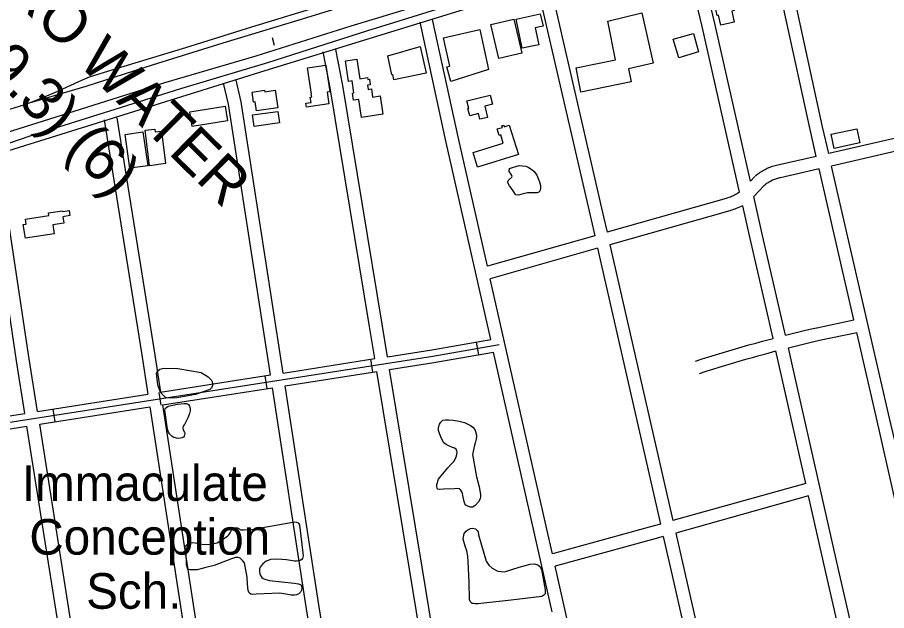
# Model space of a CAD drawing. Extents: x 3651524 to 3689615, y 505651 to 531377.
# Drawn here: x 3672779 to 3674806, y 511770 to 513153 of the extents above; entities that cross this region are included whole.
import ezdxf

# ---------------------------------------------------------------- set-up
doc = ezdxf.new("R2010")
doc.units = 0
for name, color, linetype in [('V-BLDG-IDEN', 7, 'Continuous'), ('V-BLDG-OTLN', 7, 'Continuous'), ('V-CHAN-NAID', 7, 'Continuous'), ('V-RAIL-TRAK', 7, 'Continuous'), ('V-ROAD-CNTR', 7, 'Continuous'), ('V-SITE-VEGE', 7, 'Continuous'), ('V-TOPO-SHOR', 7, 'Continuous')]:
    doc.layers.add(name, color=color, linetype=linetype)

msp = doc.modelspace()

# ---------------------------------------------------------------- linework, layer by layer
at = {"layer": 'V-BLDG-OTLN'}
for points in [[(3674419.249, 513134.831), (3674413.991, 513158.059), (3674410.776, 513157.33), (3674405.193, 513182.002), (3674407.067, 513182.426), (3674399.326, 513216.626), (3674432.782, 513224.193), (3674440.445, 513190.323), (3674445.047, 513191.366), (3674450.235, 513168.444), (3674444.613, 513167.173), (3674450.294, 513141.855)], [(3673883.17, 513136.027), (3673936.844, 513148.356), (3673954.951, 513069.538), (3673901.275, 513057.209)], [(3673941.727, 513148.945), (3673998.299, 513160.867), (3674004.602, 513132.185), (3673986.576, 513128.385), (3673994.913, 513088.826), (3673956.118, 513080.651)], [(3674235.244, 513163.683), (3674261.817, 513045.736), (3674203.694, 513032.723), (3674209.82, 513002.253), (3674093.131, 512978.787), (3674081.793, 513035.173), (3674173.54, 513053.621), (3674155.36, 513144.006)], [(3673789.368, 513003.736), (3673780.623, 513037.274), (3673787.475, 513038.829), (3673772.392, 513105.333), (3673857.525, 513124.64), (3673877.643, 513030.948)], [(3674308.071, 513102.214), (3674355.423, 513115.364), (3674367.235, 513072.797), (3674321.299, 513058.792)], [(3673718.253, 513085.177), (3673732.145, 513022.606), (3673656.838, 513007.031), (3673654.429, 513019.891), (3673652.039, 513018.754), (3673642.985, 513063.196)], [(3673624.702, 512969.807), (3673631.356, 512927.624), (3673581.465, 512919.752), (3673574.856, 512961.629), (3673562.808, 512959.729), (3673560.19, 512976.307), (3673563.639, 512976.852), (3673559.25, 513004.67), (3673551.196, 513003.398), (3673543.636, 513051.301), (3673570.412, 513055.526), (3673577.635, 513009.735), (3673595.559, 513012.563), (3673596.243, 513008.233), (3673599.76, 513008.788), (3673601.787, 512995.935), (3673595.41, 512994.93), (3673597.015, 512984.761), (3673604.272, 512985.906), (3673607.247, 512967.052)], [(3673455.468, 513035.419), (3673498.24, 513041.638), (3673507.344, 512979.054), (3673501.525, 512978.208), (3673505.482, 512951.002), (3673452.746, 512943.332), (3673451.413, 512952.499), (3673463.668, 512954.283), (3673461.841, 512966.833), (3673465.229, 512967.327), (3673464.289, 512973.792), (3673464.428, 512973.815)], [(3673386.063, 512942.255), (3673336.541, 512934.811), (3673333.411, 512955.618), (3673329.643, 512955.051), (3673326.106, 512978.568), (3673355.093, 512982.926), (3673355.63, 512979.363), (3673379.934, 512983.016)], [(3673881.673, 512971.537), (3673886.732, 512950.396), (3673868.588, 512946.052), (3673874.911, 512919.647), (3673857.365, 512915.449), (3673854.244, 512928.488), (3673833.633, 512923.557), (3673829.617, 512940.334), (3673831.446, 512940.77), (3673827.202, 512958.5)], [(3673263.288, 512946.146), (3673268.938, 512912.061), (3673186.541, 512898.399), (3673180.886, 512932.484)], [(3673386.329, 512933.715), (3673390.061, 512906.741), (3673330.777, 512898.538), (3673327.044, 512925.513)], [(3673071.63, 512886.046), (3673082.744, 512807.114), (3673041.053, 512801.24), (3673029.939, 512880.174)], [(3673114.926, 512887.61), (3673124.579, 512811.949), (3673087.108, 512807.169), (3673076.59, 512889.634), (3673099.059, 512892.501), (3673099.929, 512885.697)], [(3673852.016, 512803.64), (3673841.344, 512838.141), (3673911.691, 512859.905), (3673905.84, 512878.81), (3673902.309, 512877.718), (3673897.662, 512892.741), (3673909.929, 512896.536), (3673908.799, 512900.189), (3673912.936, 512901.467), (3673913.991, 512898.059), (3673926.016, 512901.78), (3673947.262, 512833.111)], [(3674743.263, 512860.179), (3674683.299, 512847.242), (3674676.158, 512880.348), (3674736.119, 512893.283)], [(3672864.333, 512648.445), (3672797.413, 512638.504), (3672792.708, 512670.168), (3672799.369, 512671.157), (3672797.62, 512682.929), (3672852.373, 512691.064), (3672851.439, 512697.359), (3672884.336, 512702.246), (3672884.625, 512700.304), (3672899.815, 512702.561), (3672901.564, 512690.8), (3672884.86, 512688.317), (3672887.054, 512673.553), (3672861.177, 512669.679)]]:
    msp.add_lwpolyline(points, close=True, dxfattribs=at)
at = {"layer": 'V-RAIL-TRAK'}
for points in [[(3674293.276, 513430.341), (3674148.577, 513385.209), (3674010.879, 513342.326), (3673826.701, 513284.986), (3673789.218, 513273.413), (3673656.049, 513232.301), (3673574.457, 513206.848), (3673497.978, 513182.993), (3673324.461, 513129.983), (3673170.845, 513082.119), (3673001.31, 513030.553), (3672946.39, 513013.208), (3672935.726, 513009.038), (3672921.722, 513002.79), (3672865.232, 512977.157), (3672812.873, 512955.041), (3672795.524, 512949.261), (3672675.018, 512911.838)], [(3672812.873, 512955.041), (3672939.288, 512992.845), (3673094.174, 513041.847), (3673258.817, 513093.217), (3673435.754, 513147.155), (3673641.363, 513210.928), (3673864.724, 513280.994), (3674061.944, 513342.012), (3674279.26, 513409.134), (3674317.688, 513421.53)]]:
    msp.add_lwpolyline(points, dxfattribs=at)
at = {"layer": 'V-ROAD-CNTR'}
for p, q in [((3673849.006, 512396.325), (3673854.138, 512366.767)), ((3673602.546, 512355.993), (3673607.18, 512326.353)), ((3673355.547, 512317.375), (3673360.181, 512287.735)), ((3673108.549, 512278.756), (3673113.183, 512249.116)), ((3672861.549, 512240.137), (3672866.184, 512210.499))]:
    msp.add_line(p, q, dxfattribs=at)
for points in [[(3674641.699, 512828.971), (3674627.382, 512891.179), (3674542.756, 513278.766), (3674516.963, 513388.642)], [(3674670.938, 512835.686), (3674656.656, 512897.743), (3674572.016, 513285.394), (3674546.169, 513395.498)], [(3671294.334, 512432.967), (3671352.457, 512449.955), (3671461.646, 512485.09), (3671629.739, 512537.998), (3671792.357, 512587.566), (3671992.156, 512648.584), (3672132.456, 512695.352), (3672272.375, 512737.224), (3672471.388, 512799.612), (3672680.974, 512862.027), (3672896.814, 512929.94), (3673120.483, 513000.224), (3673335.551, 513063.435), (3673557.262, 513133.321), (3673794.439, 513205.403), (3674047.647, 513287.12), (3674299.303, 513364.133)], [(3674463.095, 512745.616), (3674376.019, 513131.496), (3674328.481, 513330.011)], [(3674488.175, 512770.762), (3674405.239, 513138.292), (3674357.657, 513336.997)], [(3671355, 512405.247), (3672270.319, 512690.678), (3673356.941, 513028.814), (3674111.997, 513261.762)], [(3674020.464, 513232.382), (3674145.948, 512687.739), (3674154.041, 512652.272)], [(3673991.23, 513225.646), (3674116.706, 512681.035), (3674125.137, 512644.091)], [(3673874.758, 512573.221), (3673808.15, 512867.398), (3673747.238, 513147.889)], [(3673882.726, 512402.18), (3673778.862, 512860.902), (3673717.923, 513141.523)], [(3673612.292, 512357.517), (3673599.866, 512432.737), (3673508.287, 512988.639), (3673492.046, 513072.176)], [(3673641.933, 512362.151), (3673629.466, 512437.621), (3673537.817, 512993.941), (3673521.494, 513077.902)], [(3673398.563, 512324.1), (3673371.428, 512499.423), (3673300.932, 512956.037), (3673289.036, 513006.577)], [(3673368.923, 512319.466), (3673341.78, 512494.841), (3673271.462, 512950.303), (3673259.834, 512999.703)], [(3672981.493, 512914.222), (3673068.349, 512371.074), (3673083.12, 512274.78)], [(3673011.117, 512918.96), (3673097.987, 512375.716), (3673112.759, 512279.414)], [(3674942.136, 512897.964), (3674670.938, 512835.686)], [(3674948.832, 512868.721), (3674677.668, 512806.45)], [(3672796.521, 512229.972), (3672777.057, 512352.693), (3672714.522, 512766.978), (3672705.326, 512828.44)], [(3672826.163, 512234.606), (3672806.705, 512357.281), (3672744.187, 512771.436), (3672734.995, 512832.878)], [(3674641.7, 512828.972), (3674551.967, 512808.365)], [(3674552.194, 512808.416), (3674549.214, 512807.78), (3674546.052, 512807.01), (3674542.912, 512806.153), (3674539.794, 512805.205), (3674536.708, 512804.17), (3674533.653, 512803.05), (3674530.627, 512801.842), (3674527.64, 512800.551), (3674524.69, 512799.176), (3674521.778, 512797.717), (3674518.908, 512796.176), (3674516.085, 512794.556), (3674513.308, 512792.856), (3674510.579, 512791.077), (3674507.904, 512789.225), (3674505.278, 512787.294), (3674502.713, 512785.293), (3674500.264, 512783.271), (3674499.698, 512782.787)], [(3674824.676, 512166.741), (3674812.817, 512219.226), (3674677.667, 512806.45)], [(3674488.175, 512770.762), (3674498.579, 512781.723)], [(3674648.429, 512799.736), (3674558.681, 512779.127)], [(3674729.383, 512447.988), (3674648.428, 512799.735)], [(3674496.12, 512735.557), (3674520.337, 512761.069)], [(3674558.454, 512779.076), (3674555.894, 512778.53), (3674553.552, 512777.96), (3674551.228, 512777.325), (3674548.926, 512776.625), (3674546.642, 512775.86), (3674544.379, 512775.03), (3674542.143, 512774.138), (3674539.932, 512773.181), (3674537.748, 512772.164), (3674535.596, 512771.085), (3674533.474, 512769.946), (3674531.385, 512768.746), (3674529.33, 512767.49), (3674527.313, 512766.175), (3674525.332, 512764.803), (3674523.394, 512763.378), (3674521.493, 512761.895), (3674519.574, 512760.311), (3674519.218, 512760.005)], [(3674463.095, 512745.616), (3674455.546, 512741.087), (3674453.17, 512739.743), (3674450.763, 512738.463), (3674448.321, 512737.243), (3674445.847, 512736.087), (3674443.345, 512734.994), (3674440.819, 512733.966), (3674438.266, 512733.004), (3674435.686, 512732.106), (3674433.044, 512731.262), (3674431.639, 512730.843)], [(3674431.835, 512730.9), (3674154.042, 512652.272)], [(3674570.072, 512412.204), (3674516.71, 512644.309), (3674496.12, 512735.557)], [(3674440.005, 512702.034), (3674160.725, 512622.985)], [(3674470.23, 512714.003), (3674455.007, 512707.35), (3674451.763, 512706.03), (3674448.488, 512704.796), (3674445.184, 512703.646), (3674441.892, 512702.594), (3674440.201, 512702.091)], [(3674541.006, 512404.737), (3674487.46, 512637.647), (3674470.23, 512714.003)], [(3674125.139, 512644.091), (3673874.758, 512573.221)], [(3674160.725, 512622.985), (3674307.385, 511980.301)], [(3674131.822, 512614.804), (3673881.393, 512543.921)], [(3674131.82, 512614.805), (3674278.457, 511972.224)], [(3674026.468, 511902.945), (3674013.6, 511960.017), (3673881.392, 512543.92)], [(3674643.123, 512429.686), (3674729.382, 512447.989)], [(3674570.072, 512412.204), (3674594.94, 512418.328), (3674610.744, 512422.139), (3674626.567, 512425.871), (3674642.393, 512429.522), (3674642.907, 512429.639)], [(3674649.349, 512400.34), (3674736.111, 512418.749)], [(3674953.433, 511461.934), (3674929.651, 511566.043), (3674783.567, 512212.556), (3674736.112, 512418.748)], [(3673641.933, 512362.151), (3673745.066, 512378.276), (3673882.726, 512402.18)], [(3674360.407, 512351.869), (3674375.85, 512356.828), (3674391.353, 512361.722), (3674406.88, 512366.54), (3674422.431, 512371.281), (3674438.005, 512375.945), (3674453.602, 512380.532), (3674469.222, 512385.042), (3674484.863, 512389.474), (3674500.527, 512393.829), (3674516.211, 512398.106), (3674541.006, 512404.737)], [(3674576.795, 512382.96), (3674602.044, 512389.182), (3674617.704, 512392.957), (3674633.383, 512396.655), (3674649.095, 512400.28), (3674649.565, 512400.387)], [(3671331.153, 511994.772), (3672021.215, 512092.876), (3672671.093, 512195.178), (3673747.508, 512363.476), (3673902.03, 512390.308)], [(3674369.579, 512323.305), (3674384.952, 512328.242), (3674400.315, 512333.092), (3674415.7, 512337.866), (3674431.109, 512342.563), (3674446.541, 512347.185), (3674461.994, 512351.73), (3674477.472, 512356.198), (3674492.971, 512360.59), (3674508.491, 512364.905), (3674524.033, 512369.144), (3674547.731, 512375.483)], [(3674617.366, 512066.852), (3674557.16, 512334.469), (3674547.731, 512375.483)], [(3674799.737, 511403.525), (3674693.282, 511866.084), (3674586.414, 512341.123), (3674576.795, 512382.96)], [(3673398.563, 512324.1), (3673612.292, 512357.517)], [(3673646.822, 512332.552), (3673749.95, 512348.676), (3673889.36, 512372.883)], [(3674026.286, 511767.349), (3673984.338, 511953.405), (3673889.36, 512372.883)], [(3673112.759, 512279.414), (3673368.923, 512319.466)], [(3673403.151, 512294.453), (3673617.182, 512327.917)], [(3673717.976, 511715.748), (3673693.356, 511866.8), (3673617.182, 512327.917)], [(3673747.621, 511720.356), (3673722.96, 511871.658), (3673646.822, 512332.552)], [(3673498.391, 511681.623), (3673480.563, 511794.288), (3673403.151, 512294.453)], [(3672826.163, 512234.606), (3673083.12, 512274.78)], [(3673117.308, 512249.761), (3673373.511, 512289.819)], [(3673468.746, 511677.018), (3673450.923, 511789.65), (3673373.511, 512289.819)], [(3672830.862, 512204.975), (3673087.668, 512245.127)], [(3673087.668, 512245.127), (3673166.702, 511729.88), (3673181.828, 511632.43)], [(3673117.308, 512249.761), (3673196.352, 511734.454), (3673211.473, 511637.037)], [(3672247.299, 512143.65), (3672668.768, 512209.997), (3672796.521, 512229.972)], [(3672250.052, 512113.714), (3672673.418, 512180.359), (3672801.221, 512200.341)], [(3672898.074, 511588.229), (3672882.026, 511690.881), (3672801.221, 512200.341)], [(3672927.715, 511592.852), (3672911.66, 511695.547), (3672830.862, 512204.975)], [(3674617.367, 512066.852), (3674307.386, 511980.301)], [(3674623.959, 512037.546), (3674314.067, 511951.019)], [(3674770.915, 511395.004), (3674664.03, 511859.428), (3674623.959, 512037.545)], [(3674278.458, 511972.224), (3674251.917, 511964.813), (3674026.467, 511902.946)], [(3674314.067, 511951.02), (3674335.156, 511858.606), (3674462.414, 511297.968)], [(3674285.14, 511942.942), (3674259.921, 511935.901), (3674033.073, 511873.65)], [(3674285.139, 511942.943), (3674305.904, 511851.948), (3674434.292, 511286.331)], [(3674169.849, 511266.995), (3674033.073, 511873.649)]]:
    msp.add_lwpolyline(points, dxfattribs=at)
at = {"layer": 'V-SITE-VEGE'}
for points in [[(3673926.555, 512800.904), (3673935.382, 512803.476), (3673941.46, 512805.064), (3673948.915, 512807.437), (3673964.619, 512805.907), (3673970.122, 512803.565), (3673978.378, 512798.483), (3673983.69, 512793.392), (3673989.795, 512784.969), (3673993.545, 512777.129), (3673996.509, 512769.283), (3673998.493, 512760.657), (3673999.095, 512754.963), (3673998.323, 512750.251), (3673997.152, 512747.894), (3673995.194, 512745.532), (3673991.274, 512743.951), (3673987.544, 512743.55), (3673980.479, 512743.925), (3673973.804, 512744.107), (3673968.113, 512743.894), (3673958.696, 512741.32), (3673947.125, 512738.739), (3673941.235, 512739.507), (3673938.675, 512742.446), (3673936.508, 512746.169), (3673929.222, 512756.161), (3673926.266, 512760.47), (3673923.309, 512765.371), (3673922.514, 512769.49), (3673924.075, 512773.223), (3673932.103, 512780.113), (3673932.49, 512782.667), (3673932.093, 512784.627), (3673929.924, 512788.155), (3673927.366, 512791.289), (3673925.789, 512793.837), (3673925.392, 512795.602), (3673925.39, 512796.583), (3673926.365, 512798.94)], [(3673228.015, 512285.941), (3673193.987, 512274.24), (3673151.291, 512266.257), (3673136.134, 512265.432), (3673127.075, 512266.395), (3673123.727, 512267.961), (3673119.385, 512271.887), (3673112.87, 512278.76), (3673106.726, 512296.265), (3673103.505, 512324.013), (3673106.05, 512329.532), (3673110.767, 512332.694), (3673120.407, 512335.476), (3673152.692, 512334.769), (3673207.246, 512325.064), (3673224.005, 512315.461), (3673230.518, 512308.389), (3673233.09, 512303.67), (3673233.493, 512299.341), (3673233.506, 512295.009), (3673231.746, 512289.297)], [(3673141.847, 512174.206), (3673138.685, 512176.694), (3673133.805, 512182.47), (3673131.034, 512186.144), (3673128.912, 512192.976), (3673122.621, 512237.8), (3673123.139, 512240.561), (3673124.054, 512242.142), (3673130.751, 512246.498), (3673151.909, 512251.286), (3673167.814, 512253.3), (3673173.471, 512253.048), (3673177.814, 512250.826), (3673180.585, 512246.756), (3673182.044, 512242.421), (3673181.933, 512235.582), (3673180.497, 512229.926), (3673176.448, 512219.262), (3673168.332, 512203.859), (3673165.451, 512200.037), (3673164.932, 512196.353), (3673165.34, 512191.884), (3673168.246, 512186.107), (3673169.307, 512182.824), (3673168.789, 512180.059), (3673167.744, 512177.163), (3673165.909, 512174.792), (3673163.153, 512173.075), (3673159.604, 512172.277), (3673155.006, 512171.74), (3673149.742, 512172.252)], [(3673789.435, 512110.732), (3673796.298, 512117.829), (3673799.628, 512122.949), (3673801.777, 512128.654), (3673803.331, 512134.358), (3673804.109, 512139.474), (3673803.509, 512142.812), (3673801.731, 512146.544), (3673798.186, 512149.091), (3673793.265, 512150.848), (3673786.181, 512153.779), (3673778.7, 512157.693), (3673772.992, 512161.41), (3673767.657, 512171.82), (3673762.91, 512182.816), (3673760.925, 512190.281), (3673760.909, 512196.965), (3673763.051, 512205.03), (3673766.184, 512209.757), (3673771.089, 512213.898), (3673777.573, 512215.291), (3673785.044, 512214.719), (3673795.071, 512214.547), (3673809.43, 512212.227), (3673821.82, 512209.11), (3673835.8, 512201.676), (3673841.117, 512197.561), (3673845.849, 512192.265), (3673847.433, 512188.141), (3673849.02, 512182.05), (3673849.821, 512176.743), (3673848.854, 512169.663), (3673847.101, 512163.37), (3673844.76, 512156.286), (3673840.492, 512134.061), (3673849.272, 512082.378), (3673855.819, 512058.607), (3673858.617, 512040.723), (3673859.022, 512035.22), (3673857.658, 512031.09), (3673854.332, 512024.004), (3673846.296, 512015.332), (3673840.015, 512011.582), (3673835.493, 512011.374), (3673830.573, 512012.737), (3673824.667, 512016.068), (3673822.496, 512019.598), (3673820.714, 512024.901), (3673819.516, 512031.78), (3673817.728, 512039.048), (3673816.539, 512043.566), (3673815.152, 512047.498), (3673812.782, 512051.42), (3673809.041, 512054.361), (3673804.912, 512054.744), (3673797.834, 512054.136), (3673772.281, 512053.089), (3673763.239, 512052.475), (3673759.111, 512053.644), (3673757.728, 512054.625), (3673756.735, 512059.536), (3673757.116, 512064.454), (3673761.212, 512076.848), (3673766.891, 512084.727), (3673782.378, 512102.852)], [(3673180.759, 511865.292), (3673177.335, 511867.387), (3673175.885, 511869.357), (3673174.562, 511871.983), (3673173.634, 511875.268), (3673172.971, 511878.157), (3673173.487, 511881.446), (3673172.123, 511901.035), (3673170.116, 511914.97), (3673170.235, 511919.441), (3673173.774, 511924.053), (3673179.156, 511928.01), (3673186.123, 511928.817), (3673194.407, 511928.313), (3673204.539, 511926.103), (3673214.666, 511924.682), (3673230.051, 511925.509), (3673244.374, 511928.569), (3673257.242, 511936.493), (3673265.119, 511941.377), (3673268.926, 511944.279), (3673271.809, 511947.048), (3673274.953, 511951.92), (3673277.833, 511957.847), (3673281.505, 511961.406), (3673285.445, 511963.125), (3673288.863, 511963.659), (3673292.019, 511963.141), (3673294.917, 511961.439), (3673296.893, 511960.128), (3673299.789, 511958.693), (3673307.68, 511958.578), (3673324.771, 511959.805), (3673420.851, 511976.353), (3673424.926, 511977.151), (3673429.923, 511976.771), (3673433.741, 511975.202), (3673436.514, 511970.606), (3673445.375, 511898.176), (3673444.077, 511891.86), (3673442.373, 511889.751), (3673438.566, 511887.244), (3673434.754, 511886.183), (3673430.022, 511885.776), (3673424.762, 511886.026), (3673406.476, 511889.137), (3673395.562, 511889.237), (3673384.251, 511890.525), (3673369.657, 511889.569), (3673359.146, 511885.336), (3673351.536, 511879.661), (3673347.08, 511874.653), (3673344.849, 511871.622), (3673343.281, 511867.542), (3673343.164, 511861.888), (3673343.967, 511856.5), (3673345.818, 511852.033), (3673348.853, 511847.833), (3673352.146, 511844.949), (3673355.835, 511843.511), (3673360.965, 511842.34), (3673366.626, 511840.382), (3673424.496, 511834.744), (3673434.627, 511832.534), (3673439.498, 511830.179), (3673441.611, 511827.029), (3673442.543, 511822.427), (3673441.503, 511817.823), (3673439.145, 511813.477), (3673434.816, 511809.785), (3673429.561, 511807.141), (3673424.703, 511806.209), (3673417.598, 511806.191), (3673409.441, 511808.011), (3673390.499, 511810.856), (3673335.934, 511808.482), (3673328.179, 511807.937), (3673323.444, 511808.716), (3673319.358, 511812.122), (3673317.24, 511817.641), (3673315.1, 511831.969), (3673314.402, 511848.009), (3673308.399, 511881.919), (3673304.969, 511886.513), (3673298.116, 511892.413), (3673293.772, 511893.982), (3673287.724, 511894.097), (3673278.265, 511891.178), (3673237.802, 511875.825), (3673218.617, 511871.174), (3673209.812, 511868.784), (3673198.247, 511865.468)], [(3673853.937, 511946.937), (3673871.984, 511885.45), (3673877.905, 511876.226), (3673886.375, 511868.972), (3673899.562, 511862.715), (3673907.232, 511861.753), (3673914.705, 511860.985), (3673949.081, 511871.884), (3673974.425, 511879.026), (3673984.057, 511879.247), (3673992.517, 511876.908), (3673997.244, 511872.988), (3674001.19, 511866.314), (3674009.962, 511819.154), (3674009.395, 511809.914), (3674006.849, 511806.17), (3674002.139, 511803.012), (3673930.012, 511794.968), (3673866.921, 511787.535), (3673853.165, 511786.321), (3673845.89, 511786.302), (3673842.745, 511786.687), (3673839.597, 511787.269), (3673836.838, 511789.426), (3673834.866, 511791.779), (3673833.285, 511796.1), (3673832.001, 511836.792), (3673829.717, 511884.555), (3673829.488, 511897.335), (3673827.297, 511909.715), (3673823.336, 511920.911), (3673821.751, 511925.822), (3673819.967, 511931.715), (3673818.576, 511937.019), (3673818.955, 511942.526), (3673820.508, 511950.196), (3673825.214, 511955.713), (3673829.138, 511958.67), (3673835.814, 511961.439), (3673840.531, 511962.238), (3673846.826, 511960.681), (3673851.162, 511956.956), (3673853.333, 511953.62)]]:
    msp.add_lwpolyline(points, close=True, dxfattribs=at)
at = {"layer": 'V-TOPO-SHOR'}
msp.add_line((3673373.241, 513105.515), (3673378.015, 513088.378), dxfattribs=at)
msp.add_lwpolyline([(3672564.086, 512799.253), (3672690.173, 512836.382), (3672808.773, 512876.84), (3672994.453, 512935.38), (3673159.874, 512987.37), (3673362.675, 513047.332), (3673593.984, 513121.34), (3673809.565, 513187.831), (3673950.009, 513230.706)], dxfattribs=at)

# ---------------------------------------------------------------- texts
at = {"layer": 'V-BLDG-IDEN'}
for s, p in [('Immaculate', (3672789.204, 512026.032)), ('Conception', (3672806.801, 511900.806)), ('Sch.', (3672939.289, 511774.743))]:
    msp.add_text(s, height=82.9998, dxfattribs=at).set_placement(p)
at = {"layer": 'V-CHAN-NAID'}
for s, p in [('MARRERO WATER', (3672406.21, 513553.501)), ('INTAKE (99.3) (6)', (3672244.43, 513483.419))]:
    msp.add_text(s, height=100, rotation=315.23877, dxfattribs=at).set_placement(p)

doc.saveas('drawing.dxf')
